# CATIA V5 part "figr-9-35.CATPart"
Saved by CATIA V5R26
Part number: Part1
Bounding box of the stored display mesh (mm): x -250 to 0, y -60 to 60, z 0 to 100
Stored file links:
  D:\_Deepak\CATIA\CATIA V5-6R2016_Deepak\Resources\Part files\Partfiles\c09_catia_v5_6r2016_prt\figr-9-35.CATPart
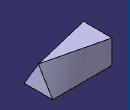
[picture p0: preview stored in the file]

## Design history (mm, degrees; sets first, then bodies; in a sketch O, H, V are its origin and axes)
Body1 (main body)
  Sketch1 on yz-plane, origin (0, 0, 0), H (0, 1, 0), V (0, 0, 1)
    point P1 (-60, 0)
    line L1 (-60, 0) -> (0, 100)
    point P2 (0, 100)
    line L2 (0, 100) -> (60, 0)
    point P3 (60, 0)
    line L3 (60, 0) -> (-60, 0)
    coincidence: P1 H, P2 V, P3 H
    horizontal: L3 H
    midpoint: O L3
  Sketch2, origin (-250, 0, 0), H (0, 1, 0), V (0, 0, 1)
    point P1 (-60, 0)
    line L1 (-60, 0) -> (60, 0)
    line L2 (60, 0) -> (60, 100)
    line L3 (60, 100) -> (-60, 100)
    line L4 (-60, 100) -> (-60, 0)
    coincidence: P1 H
    horizontal: L1 H, L3 H
    vertical: L2 V, L4 V
  Loft1: Sections (Sketch1; Sketch2), SectionCouplingPoints ({coupling CouplingPoints (vertex [element of Sketch1 | element of Sketch1]; vertex [element of Sketch2 | element of Sketch2])}; {coupling CouplingPoints (vertex [element of Sketch1 | element of Sketch1]; vertex [element of Sketch2 | element of Sketch2])}; {coupling CouplingPoints (vertex [element of Sketch1 | element of Sketch1]; vertex [element of Sketch2 | element of Sketch2])})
